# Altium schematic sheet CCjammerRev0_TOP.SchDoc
size 386 x 246 mm
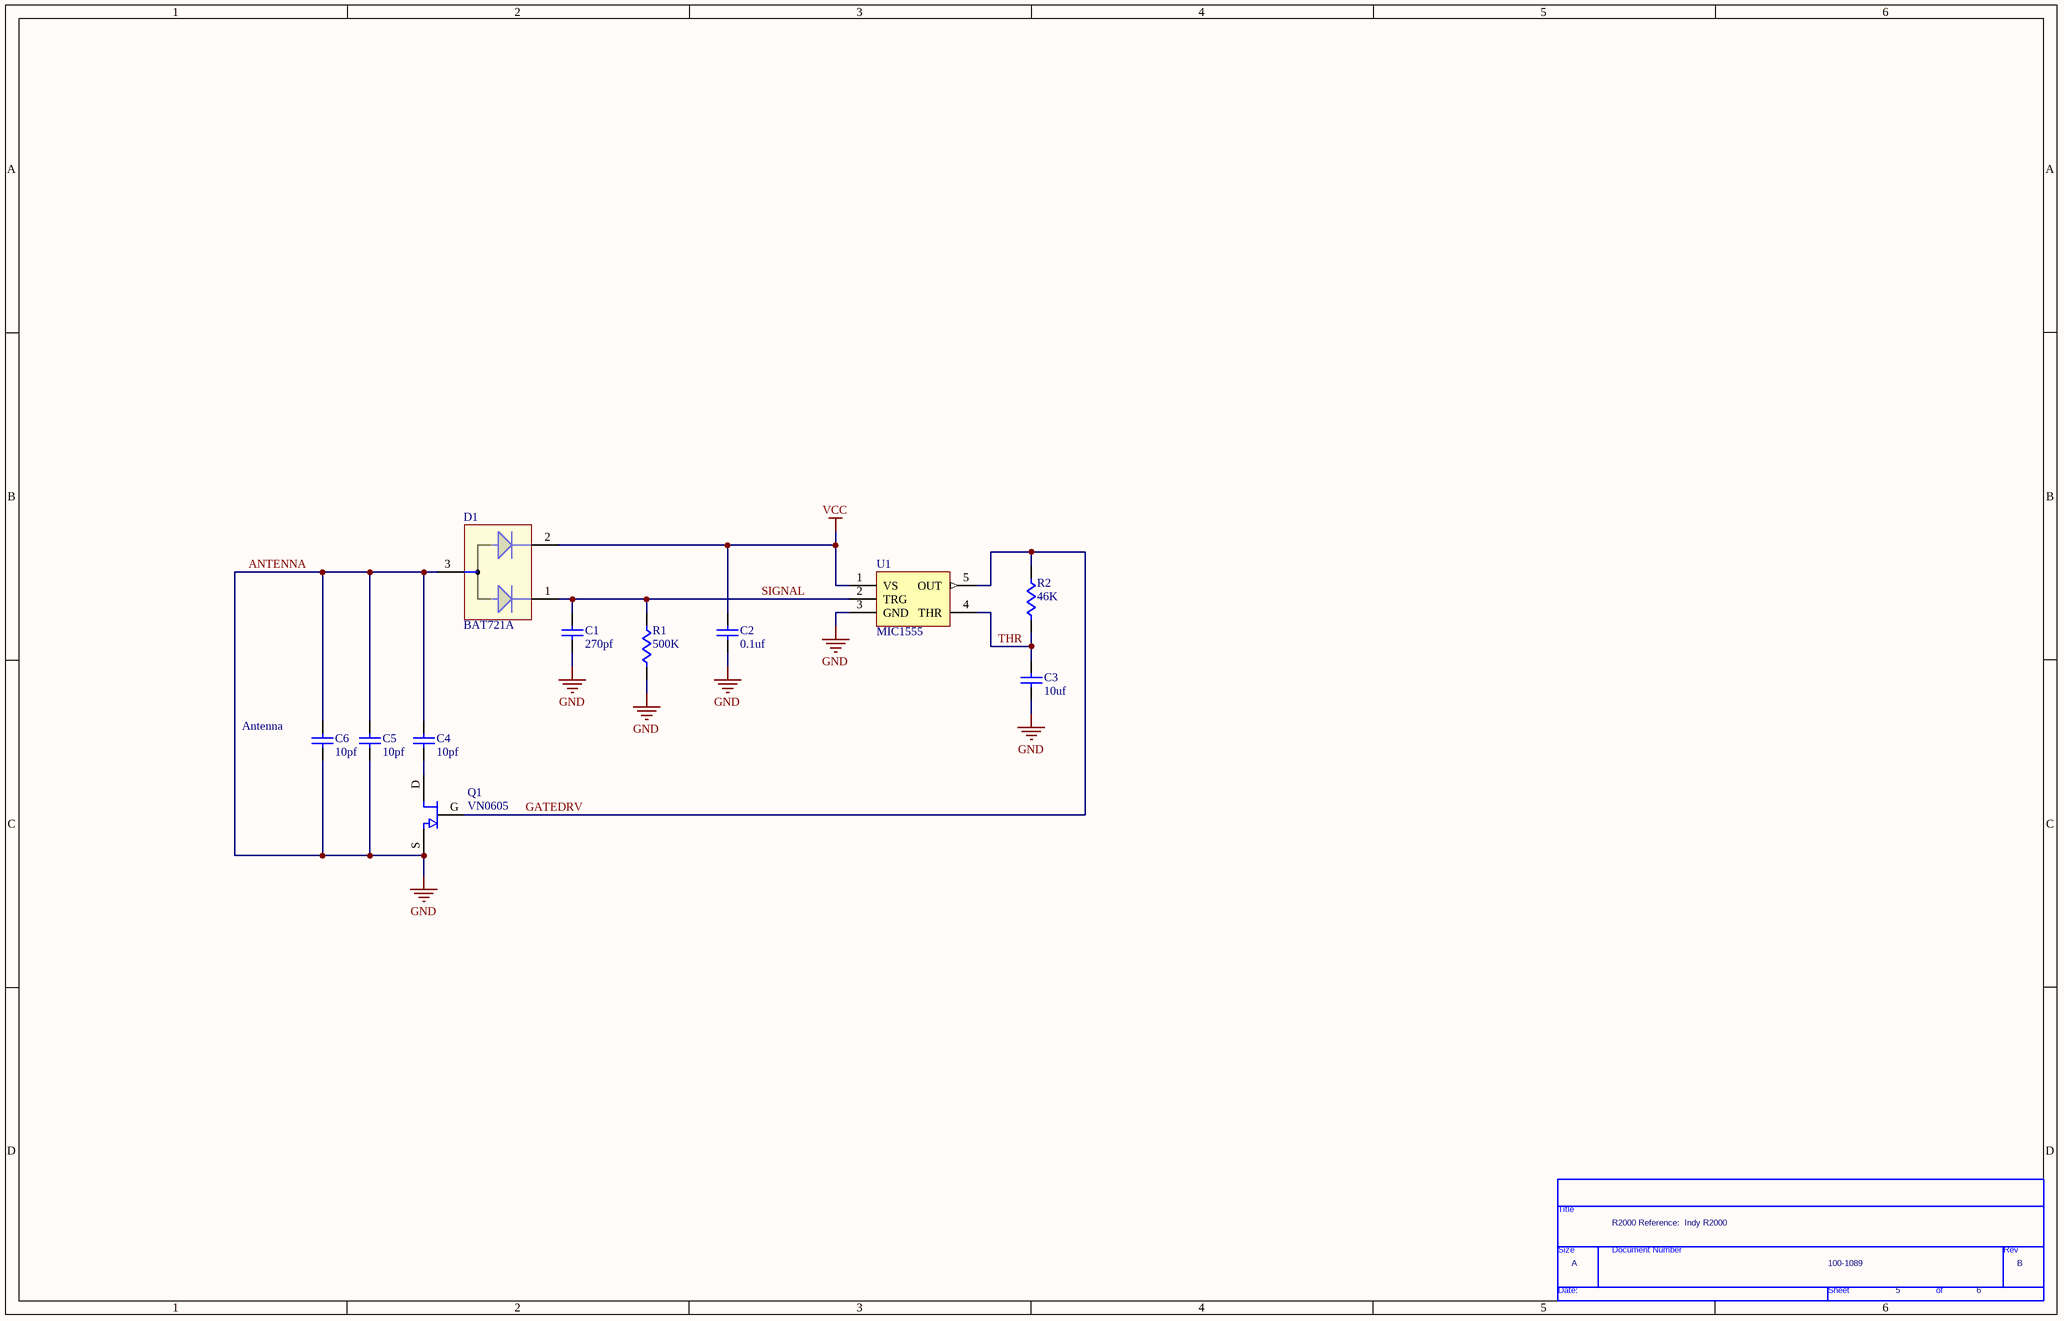
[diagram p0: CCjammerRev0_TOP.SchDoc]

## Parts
*  Page Count: 6  Page Number: 5  Page Size: A  Title: R2000 Reference:  Indy R2000  RevCode: B  Doc: 100-1089  (hidden comment: TitleBlock0)  (graphical)
C1  270pf  [0603_072205]
C2  0.1uf  [0603_072205]
C3  10uf  [0603_072205]
C4  10pf  [0603_072205]
C5  10pf  [0603_072205]
C6  10pf  [0603_072205]
D1  BAT721A  [SOT23_012105]
Q1  VN0605  [SOT23 FET_012005]
R1  500K  [0603_072205]
R2  46K  [0603_072205]
U1  MIC1555  [SOT25_030205]

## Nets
ANTENNA: C1.1 C2.1 C3.1 C4.2 C5.1 C5.2 C6.1 C6.2 D1.3(AC) Q1.S R1.1 U1.3(GND)  [also labelled GND]
VCC: C2.2 D1.2 U1.1(VS)
GATEDRV: Q1.G R2.2 U1.5(OUT)
SIGNAL: C1.2 D1.1 R1.2 U1.2(TRG)
THR: C3.2 R2.1 U1.4(THR)
NetC4_1: C4.1 Q1.D

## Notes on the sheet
- (near C6) Antenna

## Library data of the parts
C1 C3-C6 = Cap: Capacitor
C2 = Cap: Capacitor; PARTNO: TMK212BJ475KG-T; MAN: Taiyo Yuden
D1 = DIODE_DUAL_COM_AN_SOT23: PARTNO: BAT721A,215; MAN: NXP
Q1 = FET N CHANNEL: PARTNO: VN0605T; MFG: Vishay
R1 R2 = RESISTOR
U1 = MIC1555: PARTNO: MIC1555YM5; MFG: Micrel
